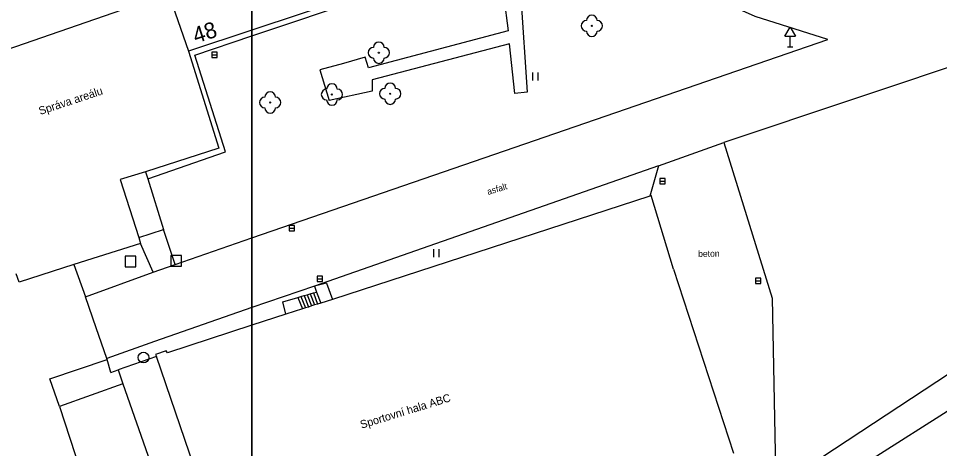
# Model space of a CAD drawing. Extents: x -493753 to -49290, y -1127285 to -112654.
# Drawn here: x -493146.9 to -493060.6, y -1126949.2 to -1126908.9 of the extents above; entities that cross this region are included whole.
import ezdxf

# ---------------------------------------------------------------- set-up
doc = ezdxf.new("R2010")
doc.units = 0
for name, color, linetype in [('Vrstva 10', 7, 'Continuous'), ('Vrstva 11', 7, 'Continuous'), ('Vrstva 22', 7, 'Continuous'), ('Vrstva 26', 7, 'Continuous'), ('Vrstva 27', 7, 'Continuous'), ('Vrstva 34', 7, 'Continuous'), ('Vrstva 36', 7, 'Continuous'), ('Vrstva 40', 7, 'Continuous'), ('Vrstva 41', 7, 'Continuous'), ('Vrstva 44', 7, 'Continuous'), ('Vrstva 5', 7, 'Continuous'), ('Vrstva 60', 7, 'Continuous'), ('Vrstva 7', 7, 'Continuous'), ('Vrstva 8', 7, 'Continuous')]:
    doc.layers.add(name, color=color, linetype=linetype)

msp = doc.modelspace()

# ---------------------------------------------------------------- linework, layer by layer
at = {"layer": 'Vrstva 10'}
for p, q in [((-493125, -1126910.55), (-493102.5, -1126902.98)), ((-493101.78, -1126904.24), (-493101, -1126910.07)), ((-493100.01, -1126904.09), (-493099.23, -1126915.8)), ((-493101, -1126910.07), (-493114.09, -1126913.54)), ((-493130.34, -1126912.34), (-493125, -1126910.55)), ((-493100.89, -1126911.29), (-493113.74, -1126914.67)), ((-493100.37, -1126915.95), (-493100.89, -1126911.29)), ((-493127.49, -1126921.39), (-493130.34, -1126912.34)), ((-493114.4, -1126912.55), (-493116.44, -1126913.13)), ((-493114.09, -1126913.54), (-493114.4, -1126912.55)), ((-493116.44, -1126913.13), (-493118.64, -1126913.73)), ((-493118.64, -1126913.73), (-493117.77, -1126916.59)), ((-493113.74, -1126914.67), (-493113.73, -1126915.73)), ((-493113.73, -1126915.73), (-493117.77, -1126916.59)), ((-493099.23, -1126915.8), (-493100.37, -1126915.95)), ((-493086.93, -1126922.72), (-493080.81, -1126920.54)), ((-493134.76, -1126923.91), (-493127.49, -1126921.39)), ((-493132.2, -1126931.94), (-493133.3, -1126928.66)), ((-493134.27, -1126932.65), (-493135.43, -1126929.98)), ((-493140.6, -1126934.98), (-493134.27, -1126932.65)), ((-493118.01, -1126933.68), (-493119.13, -1126933.96)), ((-493119.13, -1126933.96), (-493118.96, -1126934.52)), ((-493118.01, -1126933.68), (-493117.47, -1126935.21)), ((-493121.82, -1126936.59), (-493122.11, -1126935.42)), ((-493134.14, -1126939.14), (-493138.61, -1126940.73))]:
    msp.add_line(p, q, dxfattribs=at)
for points in [[(-493125, -1126929.46), (-493071.07, -1126910.9), (-493077.85, -1126908.73), (-493088.07, -1126904.15), (-493097.28, -1126898.82), (-493101.02, -1126896.27)], [(-493007.99, -1126908.18), (-493015.55, -1126900.87), (-493023.51, -1126904.99), (-493032.02, -1126908.6), (-493039.47, -1126910.76), (-493051.35, -1126912.28), (-493056.41, -1126912.39), (-493080.81, -1126920.54)], [(-493080.81, -1126920.54), (-493076.27, -1126935.1), (-493075.95, -1126951.13), (-493079.22, -1126952.19)], [(-493086.93, -1126922.72), (-493119.13, -1126933.96)], [(-493086.93, -1126922.72), (-493087.73, -1126925.54)], [(-493134.27, -1126932.65), (-493132.2, -1126931.94), (-493125, -1126929.46)], [(-493119.13, -1126933.96), (-493125, -1126935.96)], [(-493122.11, -1126935.42), (-493120.7, -1126935.02)], [(-493120.7, -1126935.02), (-493120.41, -1126934.93)], [(-493120.41, -1126934.93), (-493120.12, -1126934.85)], [(-493120.12, -1126934.85), (-493119.83, -1126934.77)], [(-493119.83, -1126934.77), (-493119.54, -1126934.69)], [(-493119.54, -1126934.69), (-493119.25, -1126934.6)], [(-493119.25, -1126934.6), (-493118.96, -1126934.52)], [(-493125, -1126935.96), (-493134.14, -1126939.14)]]:
    msp.add_lwpolyline(points, dxfattribs=at)
at = {"layer": 'Vrstva 11'}
for p, q in [((-493132.83, -1126906.59), (-493130.96, -1126911.98)), ((-493120.7, -1126935.02), (-493120.28, -1126936.1)), ((-493120.41, -1126934.93), (-493119.99, -1126936.01)), ((-493120.12, -1126934.85), (-493119.71, -1126935.92)), ((-493119.83, -1126934.77), (-493119.42, -1126935.82)), ((-493119.54, -1126934.69), (-493119.13, -1126935.73)), ((-493119.25, -1126934.6), (-493118.85, -1126935.64)), ((-493118.96, -1126934.52), (-493118.56, -1126935.55))]:
    msp.add_line(p, q, dxfattribs=at)
for points in [[(-493129.94, -1126952.26), (-493133.95, -1126940.54)], [(-493137.1, -1126943.12), (-493133.47, -1126953.43)]]:
    msp.add_lwpolyline(points, dxfattribs=at)
at = {"layer": 'Vrstva 22'}
for centre in [(-493093.16, -1126909.61), (-493113.12, -1126912.12), (-493117.51, -1126916.03), (-493112.05, -1126915.96), (-493123.3, -1126916.78)]:
    msp.add_circle(centre, 0.05, dxfattribs=at)
for centre, start, end in [((-493093.66, -1126909.61), 90, 270), ((-493093.16, -1126909.11), 360, 180), ((-493092.66, -1126909.61), 270, 90), ((-493093.16, -1126910.11), 180, 0), ((-493113.12, -1126911.62), 0, 180), ((-493113.62, -1126912.12), 90, 270), ((-493112.62, -1126912.12), 270, 90), ((-493113.12, -1126912.62), 180, 0), ((-493117.51, -1126915.53), 0, 180), ((-493112.55, -1126915.96), 90, 270), ((-493112.05, -1126915.46), 0, 180), ((-493111.55, -1126915.96), 270, 90), ((-493123.8, -1126916.78), 90, 270), ((-493123.3, -1126916.28), 0, 180), ((-493122.8, -1126916.78), 270, 90), ((-493118.01, -1126916.03), 90, 270), ((-493117.01, -1126916.03), 270, 90), ((-493117.51, -1126916.53), 180, 0), ((-493112.05, -1126916.46), 180, 0), ((-493123.3, -1126917.28), 180, 0)]:
    msp.add_arc(centre, 0.5, start, end, dxfattribs=at)
at = {"layer": 'Vrstva 26'}
for points in [[(-493136.88, -1126932.15), (-493135.88, -1126932.15), (-493135.88, -1126931.15), (-493136.88, -1126931.15)], [(-493132.61, -1126932.11), (-493131.61, -1126932.11), (-493131.61, -1126931.11), (-493132.61, -1126931.11)]]:
    msp.add_lwpolyline(points, close=True, dxfattribs=at)
at = {"layer": 'Vrstva 27'}
for p, q in [((-493128.77, -1126912.33), (-493128.27, -1126912.33)), ((-493086.8, -1126924.14), (-493086.3, -1126924.14)), ((-493121.51, -1126928.53), (-493121.01, -1126928.53)), ((-493118.9, -1126933.28), (-493118.4, -1126933.28)), ((-493077.84, -1126933.46), (-493077.34, -1126933.46))]:
    msp.add_line(p, q, dxfattribs=at)
for points in [[(-493128.77, -1126912.58), (-493128.27, -1126912.58), (-493128.27, -1126912.08), (-493128.77, -1126912.08)], [(-493086.8, -1126924.39), (-493086.3, -1126924.39), (-493086.3, -1126923.89), (-493086.8, -1126923.89)], [(-493121.51, -1126928.78), (-493121.01, -1126928.78), (-493121.01, -1126928.28), (-493121.51, -1126928.28)], [(-493118.9, -1126933.53), (-493118.4, -1126933.53), (-493118.4, -1126933.03), (-493118.9, -1126933.03)], [(-493077.84, -1126933.71), (-493077.34, -1126933.71), (-493077.34, -1126933.21), (-493077.84, -1126933.21)]]:
    msp.add_lwpolyline(points, close=True, dxfattribs=at)
msp.add_circle((-493135.16, -1126940.65), 0.5, dxfattribs=at)
at = {"layer": 'Vrstva 34'}
for p, q in [((-493075.08, -1126910.57), (-493074.58, -1126909.72)), ((-493074.58, -1126909.72), (-493074.08, -1126910.57)), ((-493075.08, -1126910.57), (-493074.08, -1126910.57)), ((-493074.58, -1126911.57), (-493074.58, -1126910.57)), ((-493074.83, -1126911.57), (-493074.33, -1126911.57))]:
    msp.add_line(p, q, dxfattribs=at)
at = {"layer": 'Vrstva 36'}
for p, q in [((-493098.69, -1126914.71), (-493098.69, -1126913.96)), ((-493098.19, -1126914.71), (-493098.19, -1126913.96)), ((-493107.96, -1126931.27), (-493107.96, -1126930.52)), ((-493107.46, -1126931.27), (-493107.46, -1126930.52))]:
    msp.add_line(p, q, dxfattribs=at)
at = {"layer": 'Vrstva 5'}
for p, q in [((-493107.38, -1126904.15), (-493125, -1126910)), ((-493151.87, -1126913.18), (-493132.83, -1126906.59)), ((-493125, -1126910), (-493130.96, -1126911.98)), ((-493130.96, -1126911.98), (-493128.09, -1126921.06)), ((-493128.09, -1126921.06), (-493134.96, -1126923.27)), ((-493134.96, -1126923.27), (-493137.35, -1126924)), ((-493085.5, -1126932.37), (-493087.62, -1126925.5)), ((-493135.61, -1126929.43), (-493133.3, -1126928.66)), ((-493135.43, -1126929.98), (-493141.7, -1126931.95)), ((-493141.7, -1126931.95), (-493146.8, -1126933.6)), ((-493085.5, -1126932.37), (-493079.9, -1126949.6)), ((-493146.8, -1126933.6), (-493147.08, -1126932.82)), ((-493117.47, -1126935.21), (-493118.56, -1126935.55)), ((-493121.82, -1126936.59), (-493125, -1126937.63)), ((-493125, -1126937.63), (-493132.91, -1126940.22)), ((-493133.03, -1126940.02), (-493134.05, -1126940.35)), ((-493134.05, -1126940.35), (-493133.95, -1126940.54)), ((-493132.91, -1126940.22), (-493133.03, -1126940.02)), ((-493133.95, -1126940.54), (-493137.53, -1126941.8)), ((-493137.53, -1126941.8), (-493137.1, -1126943.12)), ((-493137.1, -1126943.12), (-493143.04, -1126945.24)), ((-493143.04, -1126945.24), (-493135.67, -1126967.73))]:
    msp.add_line(p, q, dxfattribs=at)
for points in [[(-493137.35, -1126924), (-493135.61, -1126929.43)], [(-493134.96, -1126923.27), (-493134.76, -1126923.91), (-493133.3, -1126928.66)], [(-493087.62, -1126925.5), (-493087.73, -1126925.54), (-493117.47, -1126935.21)], [(-493135.61, -1126929.43), (-493135.43, -1126929.98)], [(-493118.56, -1126935.55), (-493118.85, -1126935.64), (-493119.13, -1126935.73), (-493119.42, -1126935.82), (-493119.71, -1126935.92), (-493119.99, -1126936.01), (-493120.28, -1126936.1), (-493121.82, -1126936.59)]]:
    msp.add_lwpolyline(points, dxfattribs=at)
at = {"layer": 'Vrstva 60'}
for points in [[(-493659.148, -1127000), (-493125, -1127000), (-493125, -1126587.478)], [(-493125, -1126587.478), (-493125, -1127000), (-492991.121, -1127000)]]:
    msp.add_lwpolyline(points, dxfattribs=at)
at = {"layer": 'Vrstva 7'}
for p, q in [((-493141.7, -1126931.95), (-493140.6, -1126934.98)), ((-493067.75, -1126950.67), (-493048.63, -1126938.48)), ((-493143.93, -1126942.64), (-493138.58, -1126940.84)), ((-493138.22, -1126942.06), (-493137.53, -1126941.8)), ((-493143.04, -1126945.24), (-493143.93, -1126942.64))]:
    msp.add_line(p, q, dxfattribs=at)
msp.add_lwpolyline([(-492984.63, -1126892.83), (-493007.99, -1126908.18), (-493072.81, -1126950.77)], dxfattribs=at)
at = {"layer": 'Vrstva 8'}
for points in [[(-493138.61, -1126940.73), (-493139.61, -1126937.86), (-493140.6, -1126934.98)], [(-493138.22, -1126942.06), (-493138.58, -1126940.84), (-493138.61, -1126940.73)]]:
    msp.add_lwpolyline(points, dxfattribs=at)

# ---------------------------------------------------------------- texts
at = {"layer": 'Vrstva 40'}
for s, rotation, p in [('asfalt', 16.94372, (-493102.876, -1126925.438)), ('beton', 0.63407, (-493083.203, -1126931.233))]:
    msp.add_text(s, height=0.6, rotation=rotation, dxfattribs=at).set_placement(p)
at = {"layer": 'Vrstva 41'}
for s, rotation, p in [('Správa areálu', 18.2337, (-493144.834, -1126917.952)), ('Sportovní hala ABC', 17.06844, (-493114.737, -1126947.311))]:
    msp.add_text(s, height=0.75, rotation=rotation, dxfattribs=at).set_placement(p)
at = {"layer": 'Vrstva 44'}
msp.add_text('48', height=1.5, rotation=17.72957, dxfattribs=at).set_placement((-493130.267, -1126911.266))

doc.saveas('drawing.dxf')
